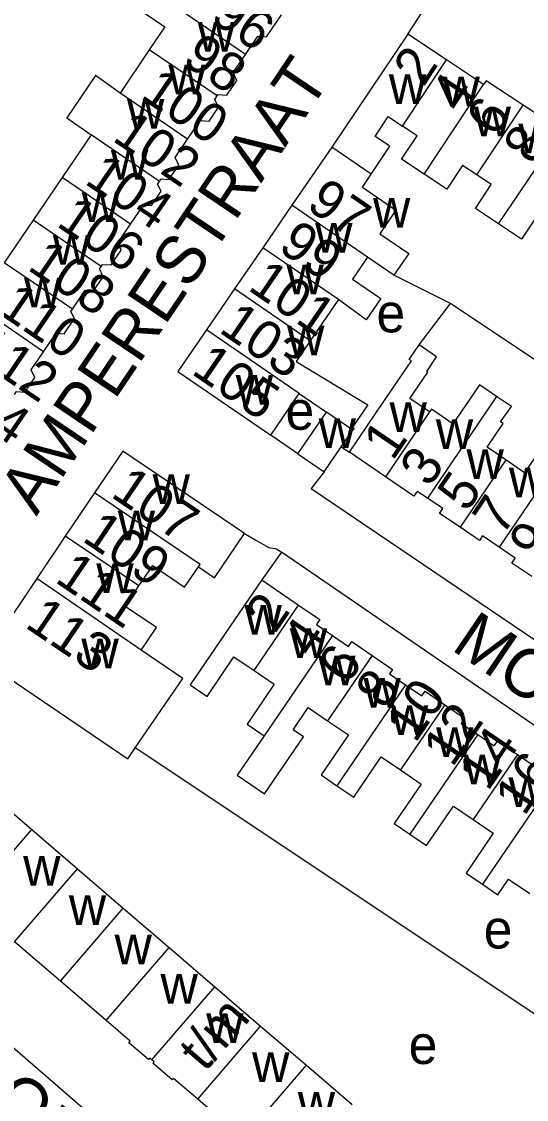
# Model space of a CAD drawing. Extents: x 159294 to 161936, y 384538 to 386517.
# Drawn here: x 159825.5 to 159877.8, y 384764.8 to 384876.4 of the extents above; entities that cross this region are included whole.
import ezdxf

# ---------------------------------------------------------------- set-up
doc = ezdxf.new("R2010")
doc.units = 0
for name, color, linetype in [('BLT_Basislijn', 7, 'Continuous'), ('BLT_Bebouwing', 7, 'Continuous'), ('BLT_Centroide', 7, 'Continuous'), ('BLT_Huisnummer', 7, 'Continuous'), ('BLT_Huisnummer_ tussenligend', 7, 'Continuous'), ('BLT_Huisnummer_reeks', 7, 'Continuous'), ('BLT_Onderverdeling_panden', 7, 'Continuous'), ('BLT_Straatnaam', 7, 'Continuous')]:
    doc.layers.add(name, color=color, linetype=linetype)

msp = doc.modelspace()

# ---------------------------------------------------------------- linework, layer by layer
at = {"layer": 'BLT_Basislijn'}
for p, q in [((159865.47, 384875.11), (159867.64, 384878.38)), ((159869.89, 384847.22), (159864.05, 384850.16)), ((159866.66, 384842.94), (159869.89, 384847.22)), ((159907.87, 384821.91), (159869.89, 384847.22)), ((159854.11, 384831.68), (159851.31, 384833.6)), ((159858.59, 384832.38), (159859.43, 384831.83)), ((159898.83, 384760.17), (159837.27, 384801.22)), ((159871.39, 384729.67), (159803.55, 384788.4))]:
    msp.add_line(p, q, dxfattribs=at)
for points in [[(159856.84, 384829.81), (159855.49, 384828.08), (159928.57, 384778.62), (159932.16, 384775.96), (159933.65, 384777.61)], [(159848.59, 384823.4), (159849.74, 384822.71), (159851.11, 384821.95), (159851.89, 384821.84), (159852.41, 384821.49)], [(159852.41, 384821.49), (159850.36, 384818.6)], [(159928.18, 384769.05), (159927.41, 384770.79), (159922.96, 384773.92), (159878.94, 384803.31), (159852.41, 384821.49)]]:
    msp.add_lwpolyline(points, dxfattribs=at)
at = {"layer": 'BLT_Bebouwing'}
for p, q in [((159865.47, 384875.11), (159857.61, 384863.43)), ((159869.49, 384872.45), (159865.47, 384875.11)), ((159838.71, 384873.51), (159835.7, 384869)), ((159873.33, 384869.9), (159869.49, 384872.45)), ((159832.7, 384864.68), (159829.7, 384860.27)), ((159857.61, 384863.43), (159853.48, 384857.4)), ((159829.7, 384860.27), (159826.7, 384855.86)), ((159860.8, 384859.27), (159864.25, 384856.9)), ((159853.48, 384857.4), (159850.47, 384853)), ((159826.7, 384855.86), (159823.7, 384851.44)), ((159850.47, 384853), (159847.54, 384848.73)), ((159847.54, 384848.73), (159844.65, 384844.49)), ((159858.3, 384847.63), (159855.38, 384843.36)), ((159851.31, 384833.6), (159854.25, 384837.91)), ((159854.25, 384837.91), (159857.06, 384835.99)), ((159854.11, 384831.68), (159857.06, 384835.99)), ((159858.59, 384832.38), (159859.79, 384834.12)), ((159856.84, 384829.81), (159858.59, 384832.38)), ((159854.11, 384831.68), (159856.84, 384829.81)), ((159863.17, 384829.29), (159859.43, 384831.83)), ((159833.06, 384827.61), (159830.02, 384823.13)), ((159830.02, 384823.13), (159827.07, 384818.77)), ((159827.07, 384818.77), (159821.37, 384810.34)), ((159821.8, 384796.84), (159826.54, 384792.77)), ((159826.54, 384792.77), (159831.27, 384788.7)), ((159831.27, 384788.7), (159836.02, 384784.63)), ((159836.02, 384784.63), (159840.76, 384780.56)), ((159829.51, 384777.05), (159824.77, 384781.12)), ((159840.76, 384780.56), (159845.49, 384776.49)), ((159834.25, 384772.99), (159829.51, 384777.05)), ((159845.49, 384776.49), (159850.24, 384772.42)), ((159850.24, 384772.42), (159854.98, 384768.35)), ((159854.98, 384768.35), (159859.71, 384764.28)), ((159848.47, 384760.77), (159843.73, 384764.84))]:
    msp.add_line(p, q, dxfattribs=at)
for points in [[(159841.64, 384877.82), (159837.57, 384880.59), (159836.25, 384878.65), (159840.32, 384875.88), (159838.71, 384873.51)], [(159848.68, 384873.02), (159849.96, 384874.91), (159850.86, 384874.85), (159852.39, 384877.1)], [(159845.74, 384868.72), (159845.85, 384868.87), (159846.75, 384868.8), (159847.78, 384870.33), (159847.39, 384871.13), (159848.68, 384873.02)], [(159835.7, 384869), (159833.14, 384870.83), (159830.17, 384866.46), (159832.7, 384864.68)], [(159877.42, 384867.76), (159873.59, 384870.3), (159873.33, 384869.9)], [(159842.69, 384864.24), (159843.99, 384866.16), (159844.91, 384866.09), (159845.9, 384867.54), (159845.5, 384868.36), (159845.74, 384868.72)], [(159881.13, 384864.77), (159881.38, 384865.14), (159877.42, 384867.76)], [(159862.1, 384864.52), (159863.46, 384866.58), (159864.95, 384865.59)], [(159867.18, 384860.61), (159864.83, 384862.17), (159866.44, 384864.6), (159864.95, 384865.59)], [(159839.77, 384859.87), (159839.95, 384860.14), (159840.75, 384860.08), (159841.76, 384861.56), (159841.39, 384862.33), (159842.69, 384864.24)], [(159861.7, 384860.63), (159863.61, 384863.52), (159862.1, 384864.52)], [(159872.63, 384860.54), (159871.15, 384861.52), (159869.52, 384859.06), (159867.18, 384860.61)], [(159836.78, 384855.45), (159838.12, 384857.42), (159838.93, 384857.36), (159839.93, 384858.85), (159839.58, 384859.59), (159839.77, 384859.87)], [(159860.8, 384859.27), (159861.7, 384860.63)], [(159874.88, 384855.49), (159872.48, 384857.08), (159874.12, 384859.55), (159872.63, 384860.54)], [(159864.25, 384856.9), (159862.57, 384854.45), (159865.58, 384852.41)], [(159833.74, 384851.07), (159833.88, 384851.28), (159834.76, 384851.22), (159835.81, 384852.76), (159835.45, 384853.5), (159836.78, 384855.45)], [(159880.37, 384855.39), (159878.91, 384856.36), (159877.27, 384853.9), (159874.88, 384855.49)], [(159861.32, 384852.03), (159859.76, 384849.75), (159862.69, 384847.74), (159861.17, 384845.53), (159858.3, 384847.63)], [(159864.05, 384850.16), (159861.32, 384852.03)], [(159865.58, 384852.41), (159864.05, 384850.16)], [(159830.76, 384846.64), (159832.09, 384848.6), (159832.95, 384848.53), (159833.95, 384850), (159833.56, 384850.81), (159833.74, 384851.07)], [(159827.75, 384842.23), (159829.06, 384844.16), (159829.91, 384844.1), (159830.97, 384845.66), (159830.6, 384846.41), (159830.76, 384846.64)], [(159844.65, 384844.49), (159841.69, 384840.19), (159851.31, 384833.6)], [(159855.38, 384843.36), (159853.93, 384841.24), (159861.36, 384836.75), (159859.76, 384834.41), (159859.92, 384834.31), (159859.79, 384834.12)], [(159824.75, 384837.82), (159824.96, 384838.13), (159825.84, 384838.06), (159826.86, 384839.57), (159826.48, 384840.36), (159827.75, 384842.23)], [(159859.43, 384831.83), (159862.24, 384835.96), (159865.86, 384841.28), (159865.64, 384841.43), (159866.66, 384842.94)], [(159867.74, 384836.01), (159865.71, 384837.4), (159867.56, 384840.12), (159867.44, 384840.2), (159868.47, 384841.71), (159866.66, 384842.94)], [(159874.67, 384837.6), (159872.91, 384838.81), (159871.82, 384837.21), (159870.16, 384834.77), (159867.93, 384836.29), (159867.74, 384836.01)], [(159875.62, 384831.03), (159873.69, 384832.35), (159875.36, 384834.81), (159875.09, 384834.99), (159876.21, 384836.56), (159874.67, 384837.6)], [(159848.59, 384823.4), (159835.99, 384831.95), (159833.06, 384827.61)], [(159881.02, 384830.96), (159879.24, 384832.17), (159877.57, 384829.71), (159875.62, 384831.03)], [(159867.51, 384827.07), (159866.46, 384827.78), (159866.12, 384827.28), (159863.17, 384829.29)], [(159870.89, 384824.06), (159868.76, 384825.5), (159869.1, 384825.99), (159867.51, 384827.07)], [(159843.81, 384819.98), (159845.47, 384818.84), (159848.59, 384823.4)], [(159874.93, 384822), (159873.22, 384823.17), (159872.9, 384822.69), (159870.89, 384824.06)], [(159878.34, 384818.95), (159876.26, 384820.36), (159876.61, 384820.87), (159874.93, 384822)], [(159837.64, 384817.98), (159839.07, 384820.09), (159842.37, 384817.85), (159843.81, 384819.98)], [(159850.36, 384818.6), (159847.55, 384814.47), (159842.96, 384807.74)], [(159850.36, 384818.6), (159854.18, 384816)], [(159837.89, 384811.35), (159839.46, 384813.67), (159836.21, 384815.87), (159837.64, 384817.98)], [(159854.18, 384816), (159856.37, 384814.51), (159856.02, 384814), (159857.68, 384812.87)], [(159857.68, 384812.87), (159859.35, 384811.73), (159859.68, 384812.22), (159861.79, 384810.79)], [(159837.27, 384801.22), (159842.2, 384808.39), (159837.89, 384811.35)], [(159861.79, 384810.79), (159863.89, 384809.35), (159863.58, 384808.89), (159865.26, 384807.74)], [(159821.37, 384810.34), (159836.51, 384800.1), (159837.27, 384801.22)], [(159842.96, 384807.74), (159844.71, 384806.55), (159847.48, 384810.63), (159849.56, 384809.22)], [(159849.56, 384809.22), (159851.64, 384807.8), (159848.84, 384803.69), (159850.61, 384802.48)], [(159865.26, 384807.74), (159866.94, 384806.6), (159867.27, 384807.08), (159869.32, 384805.68)], [(159850.61, 384802.48), (159847.8, 384798.4), (159850.66, 384796.46), (159854.68, 384802.37), (159853.61, 384803.1), (159855.17, 384805.4), (159857.18, 384804.03)], [(159869.32, 384805.68), (159871.37, 384804.28), (159871.01, 384803.75), (159872.72, 384802.59)], [(159857.18, 384804.03), (159859.34, 384802.56), (159856.51, 384798.41), (159858.14, 384797.3)], [(159872.72, 384802.59), (159874.43, 384801.43), (159874.77, 384801.92), (159876.83, 384800.52)], [(159858.14, 384797.3), (159859.88, 384796.11), (159862.72, 384800.29), (159864.72, 384798.93)], [(159876.83, 384800.52), (159878.9, 384799.11), (159878.57, 384798.63), (159880.28, 384797.47)], [(159864.72, 384798.93), (159866.87, 384797.47), (159864.08, 384793.38), (159865.7, 384792.27)], [(159865.7, 384792.27), (159867.43, 384791.1), (159870.21, 384795.19), (159872.26, 384793.8)], [(159872.26, 384793.8), (159874.33, 384792.38), (159871.52, 384788.24), (159873.21, 384787.09)], [(159873.21, 384787.09), (159874.8, 384786.01), (159875.9, 384787.62), (159878.12, 384786.14)], [(159838.99, 384768.91), (159838.76, 384769.11), (159838.63, 384768.95), (159836.6, 384770.68), (159836.74, 384770.84), (159834.25, 384772.99)], [(159843.73, 384764.84), (159841.21, 384767), (159841.08, 384766.86), (159839.09, 384768.56), (159839.22, 384768.71), (159838.99, 384768.91)]]:
    msp.add_lwpolyline(points, dxfattribs=at)
at = {"layer": 'BLT_Onderverdeling_panden'}
for p, q in [((159848.68, 384873.02), (159841.64, 384877.82)), ((159845.74, 384868.72), (159838.71, 384873.51)), ((159864.95, 384865.59), (159869.49, 384872.45)), ((159867.18, 384860.61), (159873.33, 384869.9)), ((159842.69, 384864.24), (159835.7, 384869)), ((159872.63, 384860.54), (159877.42, 384867.76)), ((159839.77, 384859.87), (159832.7, 384864.68)), ((159874.88, 384855.49), (159881.13, 384864.77)), ((159861.7, 384860.63), (159857.61, 384863.43)), ((159836.78, 384855.45), (159829.7, 384860.27)), ((159861.32, 384852.03), (159853.48, 384857.4)), ((159833.74, 384851.07), (159826.7, 384855.86)), ((159858.3, 384847.63), (159850.47, 384853)), ((159830.76, 384846.64), (159823.7, 384851.44)), ((159855.38, 384843.36), (159847.54, 384848.73)), ((159827.75, 384842.23), (159819.21, 384848.09)), ((159854.25, 384837.91), (159844.65, 384844.49)), ((159874.67, 384837.6), (159867.51, 384827.07)), ((159859.79, 384834.12), (159857.06, 384835.99)), ((159867.74, 384836.01), (159863.17, 384829.29)), ((159875.62, 384831.03), (159870.89, 384824.06)), ((159881.02, 384830.96), (159874.93, 384822)), ((159842.82, 384821), (159833.06, 384827.61)), ((159837.64, 384817.98), (159830.02, 384823.13)), ((159837.89, 384811.35), (159827.07, 384818.77)), ((159849.56, 384809.22), (159854.18, 384816)), ((159857.68, 384812.87), (159850.61, 384802.48)), ((159861.79, 384810.79), (159857.18, 384804.03)), ((159865.26, 384807.74), (159858.14, 384797.3)), ((159869.32, 384805.68), (159864.72, 384798.93)), ((159872.72, 384802.59), (159865.7, 384792.27)), ((159876.83, 384800.52), (159872.26, 384793.8)), ((159880.28, 384797.47), (159873.21, 384787.09)), ((159820.04, 384785.21), (159826.54, 384792.77)), ((159824.77, 384781.12), (159831.27, 384788.7)), ((159829.51, 384777.05), (159836.02, 384784.63)), ((159834.25, 384772.99), (159840.76, 384780.56)), ((159838.99, 384768.91), (159845.49, 384776.49)), ((159843.73, 384764.84), (159850.24, 384772.42)), ((159848.47, 384760.77), (159854.98, 384768.35))]:
    msp.add_line(p, q, dxfattribs=at)
msp.add_lwpolyline([(159843.81, 384819.98), (159843.97, 384820.22), (159842.82, 384821)], dxfattribs=at)

# ---------------------------------------------------------------- texts
at = {"layer": 'BLT_Centroide'}
for s, p in [('w', (159843.73, 384873.31)), ('w', (159840.7, 384868.88)), ('w', (159863.52, 384867.88)), ('w', (159869.08, 384867.66)), ('w', (159836.41, 384865.34)), ('w', (159872.3, 384864.55)), ('w', (159876.92, 384862.78)), ('w', (159834.74, 384860.06)), ('w', (159831.73, 384855.66)), ('w', (159861.88, 384855.09)), ('w', (159855.89, 384852.5)), ('w', (159828.73, 384851.25)), ('w', (159852.92, 384848.19)), ('w', (159825.75, 384846.84)), ('e', (159862.24, 384844.24)), ('w', (159852.98, 384841.86)), ('w', (159847.67, 384836.75)), ('e', (159852.82, 384834.16)), ('w', (159863.59, 384833.92)), ('w', (159856.25, 384832.27)), ('w', (159868.38, 384832.16)), ('w', (159871.56, 384829.05)), ('w', (159875.95, 384827.16)), ('w', (159839.06, 384826.47)), ('w', (159835.45, 384822.72)), ('w', (159833.23, 384817.25)), ('w', (159848.58, 384812.94)), ('w', (159853.27, 384810.52)), ('w', (159831.69, 384809.44)), ('w', (159856.2, 384807.69)), ('w', (159860.89, 384805.39)), ('w', (159863.73, 384802.55)), ('w', (159868.41, 384800.28)), ('w', (159871.27, 384797.45)), ('w', (159875.91, 384795.09)), ('w', (159825.66, 384786.95)), ('w', (159830.39, 384782.88)), ('e', (159873.34, 384780.45)), ('w', (159835.12, 384778.8)), ('w', (159839.88, 384774.73)), ('w', (159844.61, 384770.67)), ('e', (159865.57, 384768.49)), ('w', (159849.36, 384766.61)), ('w', (159854.09, 384762.52))]:
    msp.add_text(s, height=4, dxfattribs=at).set_placement(p)
at = {"layer": 'BLT_Huisnummer'}
for s, rotation, p in [('96', 325.7505, (159844.9, 384876.54)), ('2', 56.4897, (159867.09, 384869.56)), ('100', 325.7505, (159837.67, 384868.55)), ('6', 56.4897, (159874.61, 384864.33)), ('104', 325.7505, (159831.89, 384859.71)), ('97', 325.5921, (159854.84, 384857.13)), ('108', 325.7505, (159825.98, 384850.8)), ('101', 325.5932, (159848.8, 384848.71)), ('112', 325.7505, (159820.06, 384841.87)), ('105', 325.5958, (159842.95, 384840.02)), ('1', 55.7969, (159863.91, 384830.84)), ('107', 325.9123, (159834.6, 384827.29)), ('5', 55.7969, (159871.61, 384825.51)), ('9', 55.7969, (159878.99, 384820.41)), ('113', 325.9047, (159825.72, 384813.78)), ('2', 55.7498, (159851.73, 384812.96)), ('6', 55.7498, (159859.23, 384807.64)), ('10', 55.7498, (159866.25, 384801.62)), ('14', 55.7498, (159873.76, 384796.62))]:
    msp.add_text(s, height=4, rotation=rotation, dxfattribs=at).set_placement(p)
at = {"layer": 'BLT_Huisnummer_ tussenligend'}
for s, rotation, p in [('98', 325.7505, (159842, 384872.15)), ('4', 56.4897, (159870.91, 384866.81)), ('102', 325.7505, (159834.77, 384864.16)), ('8', 56.4897, (159878.46, 384861.44)), ('106', 325.7505, (159828.98, 384855.32)), ('99', 325.5971, (159851.92, 384852.78)), ('110', 325.7505, (159822.9, 384846.31)), ('103', 325.5932, (159845.8, 384844.34)), ('114', 325.7505, (159817.13, 384837.43)), ('3', 55.7969, (159867.72, 384828.09)), ('7', 55.7969, (159875.26, 384823.04)), ('109', 325.9123, (159831.64, 384822.71)), ('111', 325.9123, (159828.82, 384818.46)), ('4', 55.7498, (159855.55, 384810.38)), ('8', 55.7498, (159863.12, 384805.07)), ('12', 55.7498, (159870.09, 384799.11)), ('16', 55.7498, (159877.53, 384794.05))]:
    msp.add_text(s, height=4, rotation=rotation, dxfattribs=at).set_placement(p)
at = {"layer": 'BLT_Huisnummer_reeks'}
msp.add_text('t/m', height=4, rotation=49.3433, dxfattribs=at).set_placement((159844.49, 384767.58))
at = {"layer": 'BLT_Straatnaam'}
for s, rotation, p in [('AMPERESTRAAT', 56.0094, (159827.02, 384825.14)), ('MORSESTRAAT', 325.8165, (159869.85, 384811.45)), ('GROENEWOUDSEWEG', 318.5289, (159814.59, 384771.01))]:
    msp.add_text(s, height=5, rotation=rotation, dxfattribs=at).set_placement(p)

doc.saveas('drawing.dxf')
